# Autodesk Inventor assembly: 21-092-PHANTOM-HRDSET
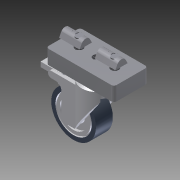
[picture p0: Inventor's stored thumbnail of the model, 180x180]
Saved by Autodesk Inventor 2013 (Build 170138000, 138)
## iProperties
Created: 2004-11
Part Number: 21-092-PHANTOM-HRDSET
Document SubType Name: Assembly
Designer: Autodesk, Inc.
Manufacturer: Standard
Standards Organization: Custom
Description: PHANTOM, CASTER, LOCKING, HARDWARE SET
Catalog Web Link: http://www.parker.com/ead/cm1.asp?cmid=809
Vendor: PARKER IPS
Mass: 442.452 g
Surface Area: 373.843 cm^2
Volume: 105.268 cm^3
Density: 4.20311 g/cm^3
CAGE: 1LJX3
Dept. ID: Product Design
Description #2: ---
Finish #1: ---
Finish #2: ---
Material ID: ---
Project Number: ---
Author: Autodesk, Inc.
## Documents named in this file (4)
- Z:\_DATEN\Test Station\Components\21-092 Caster Phantom.iam
- Z:\_DATEN\Test Station\Components\21-092 Caster.ipt
- Z:\_DATEN\Test Station\Components\21-09x_Caster_Mnt_Phantom.iam
- Z:\_DATEN\Test Station\Components\M10x25-Spring Phantom.iam
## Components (3 placed, 3 different names)
1. 21-092 Caster:1
2. 21-09x_Caster_Mnt_Phantom:1 [sub-assembly]
3. M10x25-Spring Phantom:1 [sub-assembly]
